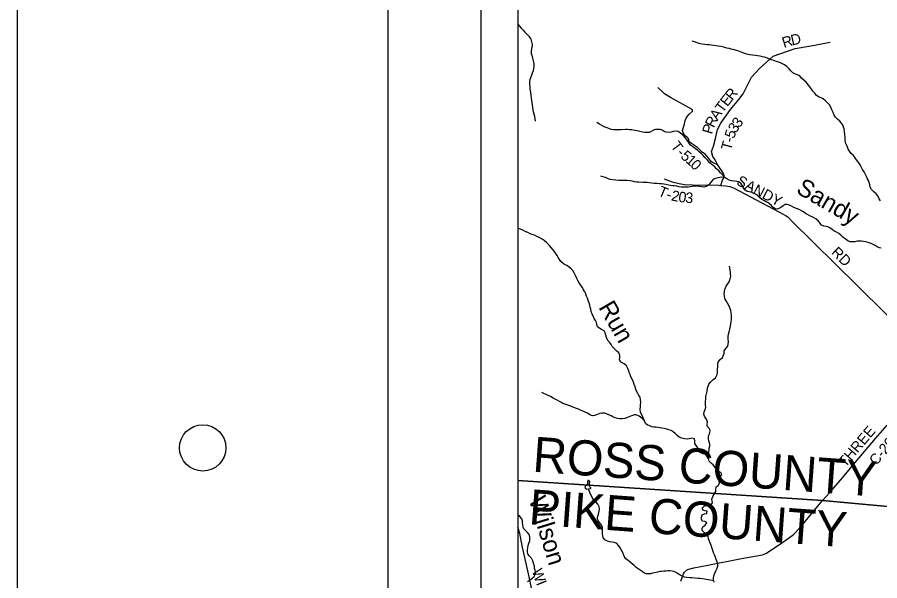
# Model space of a CAD drawing. Extents: x 5.6 to 39.6, y 0.7 to 22.7.
# Drawn here: x 5.552 to 10.203, y 17.991 to 21.029 of the extents above; entities that cross this region are included whole.
import ezdxf

# ---------------------------------------------------------------- set-up
doc = ezdxf.new("R2010")
doc.units = 0
for name, color, linetype in [('Default', 7, 'Continuous'), ('SH_Border', 7, 'Continuous'), ('SH_Cut_Line', 7, 'Continuous'), ('SH_Data', 7, 'Continuous')]:
    doc.layers.add(name, color=color, linetype=linetype)

msp = doc.modelspace()

# ---------------------------------------------------------------- linework, layer by layer
at = {"layer": 'Default'}
for points in [[(15.0518, 18.0251), (15.0518, 21.7074), (8.2518, 21.7074), (8.2518, 18.5322)], [(15.0518, 18.0251), (15.0518, 21.7074), (8.2518, 21.7074), (8.2518, 18.5322)], [(10.4881, 21.7074), (8.2518, 21.7074), (8.2518, 18.5322)], [(8.2518, 20.9913), (8.2578, 20.9821), (8.2687, 20.9707), (8.2792, 20.9599), (8.2893, 20.9492), (8.3002, 20.9373), (8.3099, 20.9277), (8.3203, 20.9102), (8.3255, 20.8961), (8.3283, 20.882), (8.3275, 20.8722), (8.3254, 20.8601), (8.3222, 20.8438), (8.3236, 20.8339), (8.3265, 20.8244), (8.3305, 20.8084), (8.3345, 20.7947), (8.3374, 20.7772), (8.3376, 20.7639), (8.3356, 20.7533), (8.3332, 20.7408), (8.3281, 20.7265), (8.323, 20.711), (8.3163, 20.694), (8.3135, 20.6807), (8.3137, 20.6689), (8.3151, 20.6553), (8.3165, 20.6408), (8.3185, 20.6245), (8.3206, 20.6055), (8.3223, 20.5937), (8.3252, 20.5785), (8.327, 20.5686), (8.3291, 20.5565), (8.3305, 20.5432), (8.3322, 20.5306), (8.334, 20.5203), (8.3369, 20.5086), (8.3405, 20.4956), (8.343, 20.4816), (8.3451, 20.4686)], [(9.7709, 20.7128), (9.7596, 20.7186), (9.7479, 20.7214), (9.7332, 20.7284), (9.7231, 20.7391), (9.7145, 20.7502), (9.7014, 20.764), (9.6886, 20.7717), (9.6781, 20.7772), (9.6679, 20.7826), (9.6562, 20.7869), (9.6453, 20.7908), (9.6313, 20.7955), (9.6193, 20.799), (9.6076, 20.8033), (9.597, 20.808), (9.5812, 20.8131), (9.5702, 20.8155), (9.5574, 20.8187), (9.5441, 20.8207), (9.532, 20.8227), (9.5158, 20.8248), (9.501, 20.8269), (9.4852, 20.8305), (9.4704, 20.8348), (9.4425, 20.8457), (9.4301, 20.85), (9.4199, 20.8524), (9.4018, 20.8568), (9.3908, 20.8595), (9.3772, 20.8627), (9.361, 20.8675), (9.3459, 20.8718), (9.3311, 20.8731), (9.3209, 20.8747), (9.2937, 20.8788), (9.2835, 20.8797), (9.2721, 20.8805), (9.2585, 20.8814), (9.243, 20.8835), (9.229, 20.8882), (9.2188, 20.8914), (9.2045, 20.8961), (9.1913, 20.9)], [(9.4419, 20.5859), (9.442, 20.5859), (9.4661, 20.6155), (9.5117, 20.7054), (9.5538, 20.7517), (9.6274, 20.8199), (9.7467, 20.8599), (9.8303, 20.8739), (9.9348, 20.8941)], [(10.2061, 20.0394), (10.1987, 20.0494), (10.1917, 20.0661), (10.1831, 20.0765), (10.1707, 20.0876), (10.1576, 20.1007), (10.1514, 20.1137), (10.1485, 20.1255), (10.1448, 20.1388), (10.1412, 20.1483), (10.1371, 20.1578), (10.1312, 20.1697), (10.1253, 20.1819), (10.1183, 20.1949), (10.1097, 20.2086), (10.1041, 20.2182), (10.0967, 20.2331), (10.0904, 20.2434), (10.0778, 20.2602), (10.0692, 20.2717), (10.0606, 20.2828), (10.0482, 20.2947), (10.0389, 20.3062), (10.0322, 20.3169), (10.0278, 20.3279), (10.0245, 20.3375), (10.0182, 20.3516), (10.0161, 20.3671), (10.0156, 20.3816), (10.0142, 20.3972), (10.0121, 20.4131), (10.01, 20.4272), (10.0075, 20.4371), (10.0035, 20.4481), (9.9953, 20.4596), (9.9874, 20.4692), (9.975, 20.4803), (9.9646, 20.4907), (9.9567, 20.5006), (9.9508, 20.5147), (9.9449, 20.53), (9.9387, 20.5433), (9.9309, 20.5563), (9.9226, 20.5662), (9.9099, 20.5789), (9.8975, 20.5885), (9.887, 20.5943), (9.8723, 20.6006), (9.8603, 20.6087), (9.8517, 20.6201), (9.8419, 20.6309), (9.8304, 20.6458), (9.8188, 20.6622), (9.8058, 20.6783), (9.7953, 20.6883), (9.7814, 20.7013), (9.7709, 20.7128)], [(9.3462, 20.1225), (9.3545, 20.1503), (9.3627, 20.1649), (9.364, 20.1737), (9.3597, 20.1859), (9.3269, 20.2358), (9.316, 20.2386), (9.3047, 20.2434), (9.295, 20.2493), (9.2794, 20.2689), (9.2631, 20.2882), (9.2441, 20.3022), (9.2377, 20.3087), (9.2296, 20.3184), (9.2195, 20.3269), (9.187, 20.3491), (9.1806, 20.3538), (9.1754, 20.3588), (9.1729, 20.3679), (9.1693, 20.3779), (9.1641, 20.3833), (9.1559, 20.3887), (9.1495, 20.3942), (9.1418, 20.4053), (9.139, 20.4179), (9.143, 20.4303), (9.1462, 20.4424), (9.1495, 20.4549), (9.154, 20.4726), (9.1588, 20.4843), (9.165, 20.4956), (9.1755, 20.5072), (9.1905, 20.5213), (9.1924, 20.5232), (9.1936, 20.5258), (9.1911, 20.5312), (9.0737, 20.597), (9.0411, 20.6162), (9.0303, 20.6262), (9.0061, 20.6498)], [(9.3269, 20.2358), (9.3157, 20.2611), (9.3023, 20.2787), (9.2949, 20.3055), (9.3053, 20.3334), (9.317, 20.3757), (9.3278, 20.4241), (9.3454, 20.4583), (9.3976, 20.5314), (9.4419, 20.5859)], [(9.1501, 20.3848), (9.1396, 20.3951), (9.1287, 20.4044), (9.116, 20.4121), (9.1046, 20.4152), (9.0894, 20.4127), (9.0773, 20.4098), (9.0648, 20.4084), (9.0515, 20.4093), (9.0402, 20.4125), (9.0285, 20.4202), (9.018, 20.4234), (9.0055, 20.4239), (8.9941, 20.4232), (8.9823, 20.4203), (8.9701, 20.4129), (8.9594, 20.4069), (8.9462, 20.4067), (8.9363, 20.4075), (8.9231, 20.4088), (8.908, 20.4124), (8.8936, 20.4163), (8.8815, 20.4191), (8.866, 20.4219), (8.8539, 20.4228), (8.8418, 20.4233), (8.8316, 20.423), (8.8081, 20.4225), (8.7959, 20.4219), (8.7815, 20.4213), (8.766, 20.4222), (8.7543, 20.4246), (8.7418, 20.4285), (8.732, 20.4324), (8.7173, 20.4383), (8.7034, 20.4456), (8.691, 20.4529), (8.6774, 20.4611)], [(10.2109, 19.7849), (10.2011, 19.7858), (10.1887, 19.792), (10.1781, 19.7986), (10.1672, 19.8044), (10.1563, 19.8095), (10.1405, 19.8153), (10.128, 19.8174), (10.1148, 19.8194), (10.1034, 19.8211), (10.0925, 19.8215), (10.0815, 19.8213), (10.0682, 19.8188), (10.0538, 19.8182), (10.0428, 19.819), (10.0304, 19.8245), (10.0154, 19.8338), (10.0052, 19.8411), (9.9925, 19.8534), (9.9813, 19.8634), (9.9692, 19.8707), (9.9557, 19.8777), (9.9459, 19.885), (9.9332, 19.8939), (9.9234, 19.8982), (9.9128, 19.9006), (9.9003, 19.903), (9.889, 19.9084), (9.8812, 19.918), (9.8719, 19.9303), (9.858, 19.9426), (9.8411, 19.9515), (9.8264, 19.9589), (9.8132, 19.9651), (9.8027, 19.9716), (9.7907, 19.9794), (9.7798, 19.9859), (9.7681, 19.9921), (9.7538, 19.9987), (9.7391, 20.0042), (9.7271, 20.0104), (9.7165, 20.0162), (9.7029, 20.0194), (9.6931, 20.0188), (9.6824, 20.0128), (9.669, 20.0042), (9.6587, 19.9982), (9.6488, 19.9942), (9.6383, 19.9962), (9.6259, 20.0047), (9.6162, 20.0162), (9.6008, 20.0289), (9.5906, 20.0343), (9.5805, 20.0393), (9.5658, 20.0463), (9.5557, 20.0555), (9.5433, 20.0671), (9.5328, 20.0748), (9.5207, 20.081), (9.5087, 20.0857), (9.4989, 20.088), (9.4875, 20.0904), (9.4747, 20.0978), (9.4666, 20.1112), (9.4617, 20.1207), (9.4558, 20.1306), (9.4419, 20.1418), (9.4321, 20.1438), (9.4185, 20.1455), (9.4026, 20.1471), (9.3901, 20.1499), (9.3777, 20.1577), (9.3676, 20.1657), (9.344, 20.1899), (9.3347, 20.2003), (9.3231, 20.2121), (9.3115, 20.2237), (9.2995, 20.2336), (9.2867, 20.2444), (9.2751, 20.2563), (9.2609, 20.2705), (9.2504, 20.2828), (9.2407, 20.2923), (9.2295, 20.3035), (9.219, 20.3116), (9.2073, 20.3208), (9.1923, 20.332), (9.1822, 20.34), (9.174, 20.3504), (9.168, 20.3603), (9.1598, 20.3721), (9.1501, 20.3848)], [(9.3676, 20.1657), (9.3502, 20.1663), (9.3403, 20.1653), (9.3297, 20.1627), (9.3171, 20.1594), (9.3042, 20.1535), (9.2915, 20.1392), (9.2815, 20.1257), (9.2658, 20.1159), (9.2533, 20.1123), (9.2405, 20.1143), (9.2299, 20.1171), (9.2144, 20.1184), (9.2037, 20.1177), (9.1927, 20.116), (9.1825, 20.1146), (9.1692, 20.1132), (9.1559, 20.1126), (9.1457, 20.1127), (9.1325, 20.1124), (9.12, 20.1145), (9.1079, 20.1176), (9.0958, 20.1196), (9.086, 20.1209), (9.075, 20.1221), (9.0644, 20.1238), (9.0482, 20.1266), (9.0383, 20.1282), (9.0255, 20.1303), (9.0141, 20.1315), (9.0012, 20.1324), (8.9869, 20.1329), (8.9729, 20.1346), (8.9589, 20.1366), (8.9486, 20.1375), (8.9365, 20.1384), (8.9244, 20.1389), (8.9024, 20.1391), (8.8926, 20.1404), (8.8805, 20.1424), (8.8684, 20.1448), (8.8578, 20.1464), (8.8393, 20.1481), (8.8234, 20.1491), (8.7961, 20.1494), (8.7794, 20.1503), (8.7617, 20.1527), (8.7496, 20.1551), (8.7341, 20.1602), (8.7235, 20.1649), (8.7099, 20.1688), (8.699, 20.1716)], [(9.04, 20.1587), (9.0838, 20.1417), (9.1217, 20.1327), (9.1493, 20.128), (9.1937, 20.1247), (9.3351, 20.1234), (9.3462, 20.1225), (9.3719, 20.1205), (9.3942, 20.1173), (9.4131, 20.1096), (9.6579, 19.9808), (9.6986, 19.9585), (9.7088, 19.952), (9.7273, 19.9321), (10.0808, 19.5833), (10.5445, 19.1246)], [(8.5391, 19.6729), (8.5286, 19.6821), (8.5146, 19.6899), (8.5033, 19.6957), (8.4936, 19.7037), (8.4835, 19.713), (8.476, 19.7237), (8.4693, 19.734), (8.4627, 19.7451), (8.4552, 19.7562), (8.447, 19.7673), (8.4388, 19.778), (8.4306, 19.7875), (8.4186, 19.8029), (8.4074, 19.8136), (8.3932, 19.8251), (8.3815, 19.8328), (8.3661, 19.8417), (8.3533, 19.8476), (8.3401, 19.8534), (8.3291, 19.8577), (8.3171, 19.862), (8.3054, 19.8682), (8.2907, 19.8748), (8.2786, 19.881), (8.2647, 19.8868), (8.2549, 19.8903), (8.2518, 19.8913)], [(9.2807, 18.6713), (9.2626, 18.6726), (9.2512, 18.675), (9.2377, 18.6801), (9.2272, 18.6867), (9.2242, 18.6966), (9.2217, 18.7072), (9.212, 18.721), (9.2057, 18.7317), (9.2047, 18.7439), (9.203, 18.7556), (9.1887, 18.7604), (9.1754, 18.7563), (9.1632, 18.7549), (9.1496, 18.7558), (9.1349, 18.7594), (9.1209, 18.7657), (9.1101, 18.7749), (9.0996, 18.7852), (9.0891, 18.7941), (9.0778, 18.8007), (9.065, 18.805), (9.0552, 18.8077), (9.0405, 18.8117), (9.0276, 18.8145), (9.017, 18.8161), (9.0068, 18.8174), (8.9947, 18.8187), (8.9838, 18.8195), (8.9736, 18.8212), (8.96, 18.8274), (8.9498, 18.8302), (8.9401, 18.8382), (8.9334, 18.8539), (8.9194, 18.8852), (8.9128, 18.8981), (8.9104, 18.9168), (8.912, 18.9285), (8.9125, 18.9384), (8.9135, 18.9536), (8.9129, 18.9665), (8.91, 18.9802), (8.9041, 18.9905), (8.8974, 19.0016), (8.8892, 19.0172), (8.883, 19.0359), (8.8783, 19.05), (8.8743, 19.061), (8.8673, 19.0771), (8.8606, 19.0912), (8.8562, 19.1026), (8.8522, 19.1137), (8.8493, 19.1236), (8.8445, 19.1358), (8.8367, 19.1499), (8.8244, 19.1607), (8.8097, 19.1684), (8.7996, 19.1818), (8.8005, 19.1928), (8.8011, 19.2057), (8.7959, 19.2191), (8.7851, 19.2295), (8.772, 19.2417), (8.76, 19.2548), (8.7537, 19.2647), (8.7444, 19.277), (8.7369, 19.2869), (8.7284, 19.3018), (8.7248, 19.3152), (8.7215, 19.3285), (8.716, 19.338), (8.7028, 19.3461), (8.6926, 19.3504), (8.681, 19.3608), (8.6778, 19.373), (8.676, 19.3833), (8.6701, 19.394), (8.663, 19.4043), (8.6564, 19.4188), (8.652, 19.4283), (8.6468, 19.4436), (8.6443, 19.4546), (8.6418, 19.4653), (8.6389, 19.4771), (8.6353, 19.4893), (8.6309, 19.5018), (8.6265, 19.5148), (8.6221, 19.5247), (8.6169, 19.538), (8.6118, 19.5491), (8.6055, 19.5598), (8.5988, 19.5713), (8.5925, 19.5812), (8.5824, 19.5965), (8.5739, 19.6099), (8.5691, 19.6202), (8.5654, 19.6301), (8.561, 19.6404), (8.5551, 19.6518), (8.5473, 19.6629), (8.5391, 19.6729)], [(9.3026, 18.4447), (9.3178, 18.4716), (9.3183, 18.4841), (9.3211, 18.4982), (9.331, 18.5049), (9.3391, 18.5181), (9.3373, 18.5276), (9.3352, 18.5386), (9.3429, 18.5503), (9.3518, 18.5638), (9.3462, 18.5742), (9.3315, 18.58), (9.3207, 18.593), (9.3121, 18.6064), (9.3047, 18.616), (9.2946, 18.6233), (9.2826, 18.6363), (9.2797, 18.6512), (9.2806, 18.6614), (9.2807, 18.6713), (9.2813, 18.683), (9.2818, 18.6963), (9.2834, 18.7069), (9.2855, 18.7175), (9.286, 18.7289), (9.2831, 18.7396), (9.2798, 18.7502), (9.2788, 18.7609), (9.2793, 18.7719), (9.2844, 18.784), (9.2876, 18.7972), (9.2854, 18.8079), (9.2724, 18.8255), (9.2725, 18.8361), (9.2741, 18.846), (9.2694, 18.8593), (9.2631, 18.8696), (9.2568, 18.8792), (9.2542, 18.8891), (9.2563, 18.9024), (9.2614, 18.9145), (9.2642, 18.9277), (9.2635, 18.9376), (9.2633, 18.9471), (9.2638, 18.96), (9.2643, 18.9695), (9.2656, 18.9839), (9.2681, 18.9983), (9.2713, 19.0127), (9.2745, 19.0286), (9.2769, 19.0407), (9.2805, 19.0509), (9.2909, 19.0637), (9.3023, 19.0735), (9.3169, 19.0851), (9.3258, 19.1025), (9.3271, 19.1146), (9.3281, 19.1309), (9.329, 19.1454), (9.3299, 19.1567), (9.3316, 19.1689), (9.3427, 19.1836), (9.355, 19.1948), (9.3605, 19.2077), (9.3629, 19.2187), (9.3642, 19.2304), (9.3727, 19.2433), (9.3831, 19.2564), (9.3858, 19.2674), (9.3864, 19.2784), (9.3843, 19.2936), (9.3849, 19.3081), (9.3865, 19.3198), (9.3905, 19.3335), (9.3941, 19.3482), (9.3973, 19.3638), (9.3994, 19.377), (9.401, 19.388), (9.4031, 19.3998), (9.4032, 19.4108), (9.4026, 19.4226), (9.4013, 19.4382), (9.3992, 19.4485), (9.3948, 19.4629), (9.3889, 19.4748), (9.3744, 19.4996), (9.3693, 19.5099), (9.3656, 19.5233), (9.3643, 19.5377), (9.3649, 19.5514), (9.3665, 19.562), (9.3751, 19.5797), (9.3836, 19.5914), (9.3905, 19.6031), (9.3964, 19.619), (9.3989, 19.633), (9.3986, 19.6441), (9.3976, 19.6555), (9.3962, 19.6654), (9.3934, 19.6775), (9.3923, 19.687)], [(8.9334, 18.8539), (8.9188, 18.8681), (8.9057, 18.8788), (8.8899, 18.8862), (8.8804, 18.886), (8.8648, 18.8801), (8.8546, 18.8764), (8.8416, 18.8712), (8.8276, 18.8664), (8.8131, 18.8643), (8.8018, 18.8644), (8.7889, 18.8653), (8.7761, 18.8689), (8.7641, 18.8751), (8.7539, 18.8805), (8.7418, 18.8859), (8.7294, 18.8903), (8.7177, 18.8942), (8.7037, 18.8947), (8.6938, 18.8925), (8.6839, 18.8892), (8.6744, 18.8852), (8.6645, 18.8818), (8.6539, 18.8812), (8.6388, 18.8859), (8.6261, 18.894), (8.6144, 18.9002), (8.602, 18.9057), (8.5888, 18.9115), (8.5778, 18.9154), (8.5673, 18.9197), (8.5533, 18.9252), (8.5398, 18.9306), (8.5254, 18.9357), (8.5145, 18.9389), (8.5047, 18.9424), (8.4945, 18.9471), (8.4825, 18.954), (8.4562, 18.9687), (8.4411, 18.9761), (8.4264, 18.985), (8.4151, 18.9908), (8.4042, 18.9959), (8.3944, 18.9994), (8.3805, 19.0068)], [(9.8937, 18.4248), (9.9312, 18.4653), (10.0012, 18.5465), (10.0708, 18.6295), (10.1794, 18.7576), (10.2421, 18.8297)], [(8.2518, 18.5322), (8.2518, 14.9074), (15.0518, 14.9074), (15.0518, 18.0251)], [(15.0518, 18.0251), (14.2655, 18.0848), (12.8677, 18.1945), (12.519, 18.2209), (12.3885, 18.2305), (10.5195, 18.3665), (9.8937, 18.4248), (8.2518, 18.5322)], [(8.2518, 18.5322), (8.2518, 14.9074), (15.0518, 14.9074), (15.0518, 18.0251)], [(15.0518, 18.0251), (14.2655, 18.0848), (12.8677, 18.1945), (12.519, 18.2209), (12.3885, 18.2305), (10.5195, 18.3665), (9.8937, 18.4248), (8.2518, 18.5322)], [(8.2518, 18.5322), (9.8937, 18.4248), (10.5195, 18.3665), (12.3885, 18.2305), (12.519, 18.2209), (12.8677, 18.1945), (14.2655, 18.0848), (15.0518, 18.0251)], [(8.2518, 18.5322), (9.8937, 18.4248), (10.5195, 18.3665), (12.3885, 18.2305), (12.519, 18.2209), (12.8677, 18.1945), (14.2655, 18.0848), (15.0518, 18.0251)], [(8.2518, 18.5322), (9.8937, 18.4248), (10.5195, 18.3665)], [(8.2518, 18.5322), (8.2518, 14.9074), (15.0518, 14.9074), (15.0518, 18.0251)], [(15.0518, 18.0251), (14.2655, 18.0848), (12.8677, 18.1945), (12.519, 18.2209), (12.3885, 18.2305), (10.5195, 18.3665), (9.8937, 18.4248), (8.2518, 18.5322)], [(8.6373, 18.5041), (8.6379, 18.5194), (8.6387, 18.5255), (8.6354, 18.5305), (8.6324, 18.532), (8.6293, 18.5309), (8.6274, 18.5252), (8.6265, 18.5188), (8.6261, 18.5135), (8.6214, 18.5055)], [(8.6372, 18.5015), (8.6379, 18.5193), (8.6387, 18.5254), (8.6354, 18.5303), (8.6324, 18.5319), (8.6293, 18.5308), (8.6274, 18.5251), (8.6265, 18.5187), (8.6261, 18.5134), (8.6214, 18.5055)], [(8.6214, 18.5055), (8.6176, 18.5025), (8.6149, 18.4994), (8.613, 18.4949), (8.6163, 18.488), (8.6223, 18.4842), (8.6326, 18.486), (8.6443, 18.4881), (8.6444, 18.4927), (8.6399, 18.4973), (8.6369, 18.5019), (8.6373, 18.5041)], [(8.6214, 18.5055), (8.6176, 18.5025), (8.6149, 18.4994), (8.613, 18.4949), (8.6163, 18.488), (8.6223, 18.4842), (8.6326, 18.486), (8.6443, 18.4881), (8.6444, 18.4927), (8.6399, 18.4973), (8.6372, 18.5015)], [(9.3076, 17.9915), (9.2888, 17.9945), (9.2779, 17.9966), (9.2669, 17.9978), (9.2571, 17.9991), (9.2461, 18.0015), (9.2317, 18.0032), (9.2211, 18.0041), (9.206, 18.0054), (9.1889, 18.0063), (9.1783, 18.0072), (9.1621, 18.0089), (9.1503, 18.0106), (9.1368, 18.0157), (9.1258, 18.0219), (9.1104, 18.0323), (9.0969, 18.0401), (9.0837, 18.0436), (9.0715, 18.0445), (9.0621, 18.0443), (9.0488, 18.0436), (9.0378, 18.0426), (9.026, 18.0416), (9.0166, 18.0406), (9.0036, 18.0377), (8.9881, 18.0345), (8.9763, 18.0316), (8.9664, 18.0294), (8.9558, 18.028), (8.9429, 18.0293), (8.9308, 18.0348), (8.9207, 18.0417), (8.9109, 18.0479), (8.9004, 18.0549), (8.8884, 18.0637), (8.8775, 18.0733), (8.8677, 18.0822), (8.8576, 18.091), (8.8471, 18.0988), (8.834, 18.1103), (8.8269, 18.121), (8.8214, 18.1336), (8.8155, 18.1466), (8.8103, 18.1565), (8.8029, 18.1695), (8.7943, 18.181), (8.7846, 18.1929), (8.7721, 18.1968), (8.76, 18.1985), (8.7475, 18.2009), (8.7336, 18.2045), (8.7204, 18.2111), (8.7118, 18.2245), (8.7089, 18.2344), (8.7071, 18.2443), (8.7081, 18.264), (8.7068, 18.2785), (8.702, 18.2918), (8.6923, 18.3037), (8.6841, 18.314), (8.6804, 18.3236), (8.6806, 18.3338), (8.6837, 18.3448), (8.6877, 18.3573), (8.6904, 18.3671), (8.6917, 18.3796), (8.69, 18.3899), (8.6822, 18.4033), (8.6721, 18.4167), (8.6594, 18.4294), (8.6527, 18.4393), (8.6482, 18.4489), (8.6404, 18.4619), (8.6326, 18.486)], [(9.13, 17.9897), (9.138, 18.0094), (9.145, 18.0287), (9.1499, 18.037), (9.1659, 18.0525), (9.2008, 18.0614), (9.2762, 18.0758), (9.4574, 18.1106), (9.5703, 18.1304), (9.5878, 18.1376), (9.6672, 18.1911), (9.7364, 18.2389), (9.7729, 18.2778), (9.8937, 18.4248)], [(9.3103, 17.9829), (9.3056, 17.9981), (9.3057, 18.0076), (9.3085, 18.0186), (9.3132, 18.0326), (9.3202, 18.0481), (9.3264, 18.0594), (9.3295, 18.0723), (9.3293, 18.0818), (9.3238, 18.0963), (9.3201, 18.1062), (9.3168, 18.1161), (9.3131, 18.1268), (9.3087, 18.1382), (9.3047, 18.1485), (9.2999, 18.1607), (9.2948, 18.1752), (9.2908, 18.187), (9.2864, 18.1996), (9.2831, 18.2091), (9.2798, 18.2198), (9.2769, 18.2305), (9.2694, 18.2404), (9.2567, 18.2504), (9.2447, 18.2631), (9.2444, 18.2726), (9.2487, 18.2824), (9.2609, 18.291), (9.2694, 18.3038), (9.2585, 18.3112), (9.2457, 18.3125), (9.2409, 18.3228), (9.2414, 18.3334), (9.2453, 18.3463), (9.2579, 18.3514), (9.2697, 18.3547), (9.2713, 18.3669), (9.2615, 18.3685), (9.2483, 18.3721), (9.2473, 18.3838), (9.2569, 18.3951), (9.2698, 18.3973), (9.2793, 18.3975), (9.2922, 18.3981), (9.3003, 18.4121), (9.2997, 18.422), (9.2979, 18.4315), (9.3026, 18.4447)], [(8.3035, 17.9877), (8.3131, 17.9952), (8.3257, 18.0034), (8.3387, 18.015), (8.3461, 18.0282), (8.3462, 18.0381), (8.344, 18.048), (8.3411, 18.0583), (8.3401, 18.0689), (8.3358, 18.0857), (8.3325, 18.0994), (8.3251, 18.1128), (8.312, 18.1251), (8.3049, 18.1365), (8.3035, 18.1464), (8.3036, 18.1559), (8.3046, 18.1703), (8.3066, 18.1809), (8.3101, 18.1931), (8.3149, 18.2067), (8.3161, 18.218), (8.3159, 18.2275), (8.3122, 18.2401), (8.3036, 18.2508), (8.2939, 18.2601), (8.2842, 18.2712), (8.2797, 18.2807), (8.2772, 18.2903), (8.2766, 18.3051), (8.276, 18.315), (8.2723, 18.3249), (8.2615, 18.3375), (8.2518, 18.3469)], [(8.4076, 17.3992), (8.4221, 17.5141), (8.4357, 17.6491), (8.437, 17.6806), (8.4356, 17.6939), (8.4398, 17.7068), (8.444, 17.7185), (8.4479, 17.7314), (8.4494, 17.7432), (8.4491, 17.7591), (8.4451, 17.7796), (8.4342, 17.7975), (8.4169, 17.8151), (8.3992, 17.833), (8.3856, 17.8498), (8.3571, 17.8997), (8.3361, 17.9267), (8.3241, 17.9518), (8.3119, 18.0119), (8.2753, 18.1719), (8.2613, 18.2468), (8.2518, 18.2798)]]:
    msp.add_lwpolyline(points, dxfattribs=at)
at = {"layer": 'SH_Border'}
msp.add_lwpolyline([(7.5518, 22.2074), (39.0518, 22.2074), (39.0518, 1.2074), (7.5518, 1.2074)], close=True, dxfattribs=at)
msp.add_circle((6.5518, 18.7074), 0.125, dxfattribs=at)
at = {"layer": 'SH_Cut_Line'}
msp.add_lwpolyline([(5.5518, 0.7074), (39.5518, 0.7074), (39.5518, 22.7074), (5.5518, 22.7074)], close=True, dxfattribs=at)
at = {"layer": 'SH_Data'}
msp.add_line((8.0518, 21.7074), (8.0518, 14.7074), dxfattribs=at)

# ---------------------------------------------------------------- texts
at = {"layer": 'Default'}
for s, height, rotation, p in [('R', 0.0568, 17.3284, (9.6859, 20.863)), ('D', 0.0568, 12.3113, (9.7292, 20.8765)), ('E', 0.0568, 51.6334, (9.3806, 20.5438)), ('R', 0.0568, 50.8623, (9.4068, 20.577)), ('T', 0.0568, 53.6204, (9.3557, 20.51)), ('A', 0.0568, 55.2207, (9.3274, 20.4693)), ('R', 0.0568, 63.2037, (9.3074, 20.4294)), ('3', 0.0568, 54.4838, (9.446, 20.4296)), ('P', 0.0568, 73.5488, (9.2976, 20.3952)), ('5', 0.0568, 70.8377, (9.4169, 20.3713)), ('3', 0.0568, 55.8654, (9.4266, 20.4009)), ('-', 0.0568, 76.6267, (9.4119, 20.3501)), ('T', 0.0568, 307.1497, (9.0726, 20.3333)), ('T', 0.0568, 74.877, (9.4003, 20.3072)), ('-', 0.0568, 316.3317, (9.1049, 20.292)), ('5', 0.0568, 320.4737, (9.1251, 20.2729)), ('1', 0.0568, 318.8077, (9.1518, 20.2509)), ('0', 0.0568, 315.2502, (9.1774, 20.2285)), ('SANDY', 0.05682, 332.092, (9.4254, 20.1291)), ('Sandy', 0.09467, 329.9522, (9.7457, 20.0849)), ('T', 0.0568, 336.8293, (9.0023, 20.0696)), ('2', 0.0568, 347.7019, (9.0748, 20.0422)), ('-', 0.0568, 342.2499, (9.0469, 20.0508)), ('0', 0.0568, 352.8253, (9.1145, 20.0338)), ('3', 0.0568, 356.0613, (9.1527, 20.0291)), ('RD', 0.05682, 315.3477, (9.9371, 19.757)), ('Run', 0.09473, 299.8935, (8.6833, 19.4658)), ('THREE', 0.05682, 49.6754, (10.0171, 18.5998)), ('C-205', 0.05682, 49.6669, (10.1832, 18.6088)), ('ROSS COUNTY', 0.189394, 355.8387, (8.3271, 18.5796)), ('PIKE COUNTY', 0.189394, 355.8387, (8.3065, 18.2962)), ('Wilson', 0.09473, 287.0187, (8.3091, 18.4305)), ('W', 0.0568, 287.9109, (8.3267, 18.0457)), ('I', 0.0568, 292.0491, (8.3485, 17.9788))]:
    msp.add_text(s, height=height, rotation=rotation, dxfattribs=at).set_placement(p)

doc.saveas('drawing.dxf')
